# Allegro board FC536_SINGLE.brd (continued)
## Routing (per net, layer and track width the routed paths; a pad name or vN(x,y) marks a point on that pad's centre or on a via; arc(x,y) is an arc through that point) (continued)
SERDES_0S_EXT_REFCLK_N: length 5.7
  TOP w0.076: U1.P28 v1(64.28,57.25)
  SIG2 w0.076: 69.14,57.67 64.27,57.67 64.14,57.54 64.14,57.4 v1(64.28,57.25)
SERDES_0S_EXT_REFCLK_P: length 6.1
  TOP w0.076: U1.P27 v1(63.78,57.25)
  SIG2 w0.076: v1(63.78,57.25) 63.93,57.4 63.93,57.62 64.18,57.87 69.14,57.87
SERDES_VREF: length 1.9
  TOP w0.203: U1.L28 v1(64.28,59.18) ; U1.L27 v1(63.78,59.18)
  BOTTOM w0.254: v1(63.78,59.18) 64.14,58.83 C99.1 ; v1(64.28,59.18) 64.42,59.32 64.7,59.32 C98.1

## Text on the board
BOTTOM: Layer 14 (BOTTOM)
Ref Des/Assembly Bottom: ASSEMBLY_BOTTOM
Ref Des/Silkscreen Bottom: 305-PD-1X-XXXX | MICROSEMI TECHNICAL SUPPORT | +1(800) 262-1060
TOP: Layer 1 (TOP)
Ref Des/Assembly Top: ASSEMBLY_TOP
Ref Des/Silkscreen Top: RT4G_DEVELOPMENT_KIT REV A | DVP-101-000XXX-001
FAB_DATA: 4.0 MILS | 6.5 MILS | 50 OHM | SINGLE | 3.5/8.0 MILS | DIFFERENTIAL | 5 / 8 MILS | 100 OHM | 5.1 / 4.9 MILS | 90 OHM | REV | 1 | INTIAL RELEASE | DESCRIPTION | REVISIONS | XXXXXXXX | DATE | APPROVAL | 10.  VIAS IN THIS REGION NEEDS VIA PLUGGING FROM BOTTOM SIDE. | 14.  IMPEDANCE TOLERANCE SHOULD BE +/- 5% ON L1, L12, L14. REST OF THE LAYRES CAN HAVE 10% TOLERANCE | 11.  BOARD MUST BE UL 94V-1 APPROVED. | 12.  FABRICATE BOARD PER IPC-A-600D STANDARD. | 13.  CLIP SILKSCREEN ON NO MASK AREA. | 17.  REMOVE UNUSED PADS IN ALL INNER LAYERS. | 18.  BOARD DIMENSIONS ARE IN INCHES | 15.  NO VENDOR LOGO, ART WORKS SHOULD NOT BE | 20.  THIS IS A ROHS COMPLIANT BOARD | 19.  WARP & TWIST: SHALL NOT EXCEED 0.005 INCHES PER INCH | 2.1. SELECTIVE HARD GOLD PLATING TO BE FLAT & | 16.  DEBURR ALL SHARP EDGES | 21.  EDGE FINGER- CHAMFER EDGES MUST BE FREE OF CUTTING BURRS | 5.  SILKSCREEN BOTH SIDES, WHITE. | 7.  SOLDER MASK TOP AND BOTTOM SIDES WITH | 6.  FABRICATE PER DIMENSIONS SHOWN. | PLATING IN HOLES TO BE 0.001 MIN. THICK. | 4.  HOLE SIZES ARE AFTER PLATING. | 3.  HOLES TO BE PLATED THROUGH. | 9.  APPLY THIEVING AS REQUIRED. | 8.  TOTAL BOARD THICKNESS:  62 mil+/- 6 mil | SOLDER MASK.  COLOR GREEN. | LIQUID PHOTO IMAGABLE OR DRY FILM | 14 LAYER CONSTRUCTION. | 2.  GENERAL PLATING - FLASH GOLD | NOTES: UNLESS OTHERWISE SPECIFIED | 1.  MATERIAL: FR-4. | ABOVE THE SOLDER RESIST SURFACE ON TOP AND BOTTOM | THE VIAS SHOULD BE SMOOTHENED TO BOARD SURFACE ON TOP AND BOTTOM | GOLD PLATING ON PAD SHOULD BE THE SAME LEVEL OR | FOR SELECTIVE PLATING SEE BELOW | CHANGED WITHOUT PRIOR APPROVAL FROM PACTRON | PLATED 30uIN(MINIMUM) OF Au OVER 150-200uIN OF Ni. | NOTE: DIELECTRIC GLASS STYLE SHOULD NOT BE CHANGED WITHOUT PRIOR APPROVAL FROM PACTRON. | GLASS STYLE | DIELECTRIC | SHOULD NOT BE CHANGED FROM ABOVE STATED VALUES. | FINISHED TRACE WIDTH,AIR GAP OF 100 OHM DIFFERENTIAL AND 50 OHM SIGNLE ENDED | 2116 | STACKUP - 14 LAYERS | REFER STACKUP | CONTROLLED IMPEDANCE REQUIRED
User.17: FIGURE | SIZE | 125.0 | DRILL CHART: TOP to BOTTOM | ALL UNITS ARE IN MILS | TOLERANCE | +2.0/-2.0 | PLATED | NON-PLATED | QTY | 2
User.19: DATE: | FILM LAYER: | NAME: | XXXXXXXX | XXXXXXXXXXXXXXXXXXXX | REV: | A | PACTRON
User.20: FAB | PROJECT NAME | PART NUMBER | PACTRON | DATE | 3000 PATRICK HENRY DRIVE, SANTA CLARA, CA 95054. | 408-329-5500(PHONE), 408-747-1239(FAX). | XXXXXXXXXXXXXXXXXXXXXX | DVP-101-000XXX-001 | XXXXXXXX | 305-PD-15-XXXX | REV : | A
User.23: DIELECTRIC (4.00 mils) | DIELECTRIC (4.50 mils) | DIELECTRIC (3.50 mils) | DIELECTRIC (2.00 mils) | TOP (1.40 mils) | L2_GND1 (0.60 mils) | L3_SIG1 (0.60 mils) | L4_GND2 (0.60 mils) | L5_SIG2 (0.60 mils) | L6_GND3 (0.60 mils) | L7_PWR1 (1.30 mils) | L8_PWR2 (1.30 mils) | L9_GND4 (0.60 mils) | L10_SIG3 (0.60 mils) | L11_GND5 (0.60 mils) | L12_SIG4 (0.60 mils) | L13_GND6 (0.60 mils) | BOTTOM (1.40 mils) | FR-4
